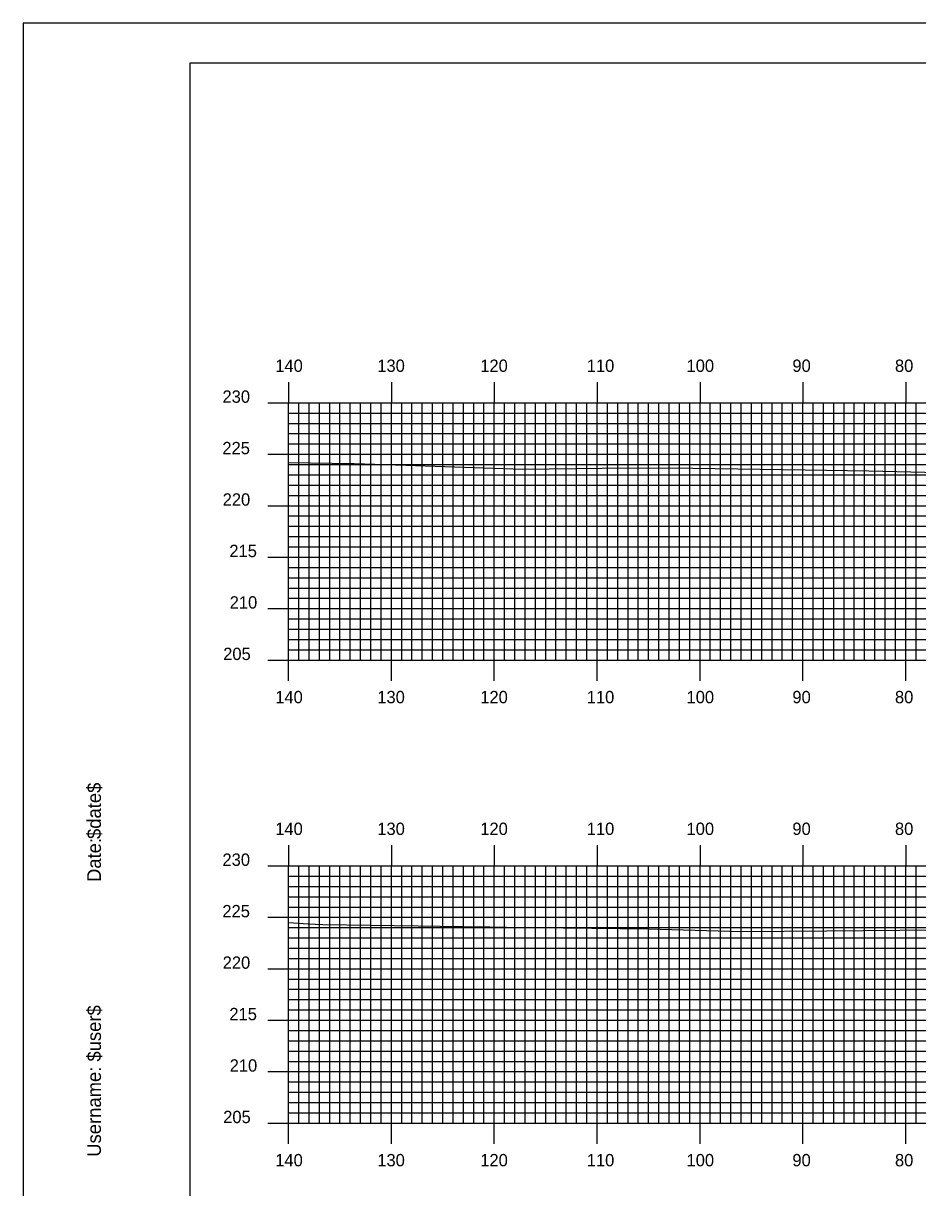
# Model space of a CAD drawing. Extents: x 1820424 to 1820768, y 442591 to 442811.
# Drawn here: x 1820424.4 to 1820511.4, y 442697.4 to 442810.5 of the extents above; entities that cross this region are included whole.
import ezdxf

# ---------------------------------------------------------------- set-up
doc = ezdxf.new("R2010")
doc.units = 0
for name, color, linetype in [('BORDER', 7, 'Continuous'), ('H_V ANNOTATION', 7, 'Continuous'), ('MAJOR', 7, 'Continuous'), ('MINOR', 7, 'Continuous'), ('PLOT BOUNDARY', 7, 'Continuous'), ('S_Roadway_Centerline', 7, 'Continuous')]:
    doc.layers.add(name, color=color, linetype=linetype)

msp = doc.modelspace()

# ---------------------------------------------------------------- linework, layer by layer
at = {"layer": 'BORDER'}
msp.add_lwpolyline([(1820440.6, 442596.67), (1820760.6, 442596.67), (1820760.6, 442806.67), (1820440.6, 442806.67)], close=True, dxfattribs=at)
at = {"layer": 'MAJOR'}
for p, q in [((1820450.2, 442775.67), (1820450.2, 442773.67)), ((1820460.2, 442775.67), (1820460.2, 442773.67)), ((1820470.2, 442775.67), (1820470.2, 442773.67)), ((1820480.2, 442775.67), (1820480.2, 442773.67)), ((1820490.2, 442775.67), (1820490.2, 442773.67)), ((1820500.2, 442775.67), (1820500.2, 442773.67)), ((1820510.2, 442775.67), (1820510.2, 442773.67)), ((1820448.2, 442773.67), (1820450.2, 442773.67)), ((1820450.2, 442773.67), (1820730.2, 442773.67)), ((1820450.2, 442748.67), (1820450.2, 442773.67)), ((1820450.2, 442748.67), (1820450.2, 442773.67)), ((1820450.2, 442773.67), (1820730.2, 442773.67)), ((1820460.2, 442748.67), (1820460.2, 442773.67)), ((1820470.2, 442748.67), (1820470.2, 442773.67)), ((1820480.2, 442748.67), (1820480.2, 442773.67)), ((1820490.2, 442748.67), (1820490.2, 442773.67)), ((1820500.2, 442748.67), (1820500.2, 442773.67)), ((1820510.2, 442748.67), (1820510.2, 442773.67)), ((1820448.2, 442768.67), (1820450.2, 442768.67)), ((1820450.2, 442768.67), (1820730.2, 442768.67)), ((1820448.2, 442763.67), (1820450.2, 442763.67)), ((1820450.2, 442763.67), (1820730.2, 442763.67)), ((1820448.2, 442758.67), (1820450.2, 442758.67)), ((1820450.2, 442758.67), (1820730.2, 442758.67)), ((1820448.2, 442753.67), (1820450.2, 442753.67)), ((1820450.2, 442753.67), (1820730.2, 442753.67)), ((1820448.2, 442748.67), (1820450.2, 442748.67)), ((1820450.2, 442748.67), (1820730.2, 442748.67)), ((1820450.2, 442748.67), (1820730.2, 442748.67)), ((1820450.2, 442746.66), (1820450.2, 442748.67)), ((1820460.2, 442746.66), (1820460.2, 442748.67)), ((1820470.2, 442746.66), (1820470.2, 442748.67)), ((1820480.2, 442746.66), (1820480.2, 442748.67)), ((1820490.2, 442746.66), (1820490.2, 442748.67)), ((1820500.2, 442746.66), (1820500.2, 442748.67)), ((1820510.2, 442746.66), (1820510.2, 442748.67)), ((1820450.2, 442730.67), (1820450.2, 442728.67)), ((1820460.2, 442730.67), (1820460.2, 442728.67)), ((1820470.2, 442730.67), (1820470.2, 442728.67)), ((1820480.2, 442730.67), (1820480.2, 442728.67)), ((1820490.2, 442730.67), (1820490.2, 442728.67)), ((1820500.2, 442730.67), (1820500.2, 442728.67)), ((1820510.2, 442730.67), (1820510.2, 442728.67)), ((1820448.2, 442728.67), (1820450.2, 442728.67)), ((1820450.2, 442728.67), (1820730.2, 442728.67)), ((1820450.2, 442703.67), (1820450.2, 442728.67)), ((1820450.2, 442703.67), (1820450.2, 442728.67)), ((1820450.2, 442728.67), (1820730.2, 442728.67)), ((1820460.2, 442703.67), (1820460.2, 442728.67)), ((1820470.2, 442703.67), (1820470.2, 442728.67)), ((1820480.2, 442703.67), (1820480.2, 442728.67)), ((1820490.2, 442703.67), (1820490.2, 442728.67)), ((1820500.2, 442703.67), (1820500.2, 442728.67)), ((1820510.2, 442703.67), (1820510.2, 442728.67)), ((1820448.2, 442723.67), (1820450.2, 442723.67)), ((1820450.2, 442723.67), (1820730.2, 442723.67)), ((1820448.2, 442718.67), (1820450.2, 442718.67)), ((1820450.2, 442718.67), (1820730.2, 442718.67)), ((1820448.2, 442713.67), (1820450.2, 442713.67)), ((1820450.2, 442713.67), (1820730.2, 442713.67)), ((1820448.2, 442708.67), (1820450.2, 442708.67)), ((1820450.2, 442708.67), (1820730.2, 442708.67)), ((1820448.2, 442703.67), (1820450.2, 442703.67)), ((1820450.2, 442703.67), (1820730.2, 442703.67)), ((1820450.2, 442703.67), (1820730.2, 442703.67)), ((1820450.2, 442701.66), (1820450.2, 442703.67)), ((1820460.2, 442701.66), (1820460.2, 442703.67)), ((1820470.2, 442701.66), (1820470.2, 442703.67)), ((1820480.2, 442701.66), (1820480.2, 442703.67)), ((1820490.2, 442701.66), (1820490.2, 442703.67)), ((1820500.2, 442701.66), (1820500.2, 442703.67)), ((1820510.2, 442701.66), (1820510.2, 442703.67))]:
    msp.add_line(p, q, dxfattribs=at)
at = {"layer": 'MINOR'}
for p, q in [((1820450.2, 442772.67), (1820730.2, 442772.67)), ((1820450.2, 442772.67), (1820452.21, 442772.67)), ((1820451.2, 442748.67), (1820451.2, 442773.67)), ((1820452.2, 442748.67), (1820452.2, 442773.67)), ((1820453.2, 442748.67), (1820453.2, 442773.67)), ((1820454.2, 442748.67), (1820454.2, 442773.67)), ((1820455.2, 442748.67), (1820455.2, 442773.67)), ((1820456.2, 442748.67), (1820456.2, 442773.67)), ((1820457.2, 442748.67), (1820457.2, 442773.67)), ((1820458.2, 442748.67), (1820458.2, 442773.67)), ((1820459.2, 442748.67), (1820459.2, 442773.67)), ((1820461.2, 442748.67), (1820461.2, 442773.67)), ((1820462.2, 442748.67), (1820462.2, 442773.67)), ((1820463.2, 442748.67), (1820463.2, 442773.67)), ((1820464.2, 442748.67), (1820464.2, 442773.67)), ((1820465.2, 442748.67), (1820465.2, 442773.67)), ((1820466.2, 442748.67), (1820466.2, 442773.67)), ((1820467.2, 442748.67), (1820467.2, 442773.67)), ((1820468.2, 442748.67), (1820468.2, 442773.67)), ((1820469.2, 442748.67), (1820469.2, 442773.67)), ((1820471.2, 442748.67), (1820471.2, 442773.67)), ((1820472.2, 442748.67), (1820472.2, 442773.67)), ((1820473.2, 442748.67), (1820473.2, 442773.67)), ((1820474.2, 442748.67), (1820474.2, 442773.67)), ((1820475.2, 442748.67), (1820475.2, 442773.67)), ((1820476.2, 442748.67), (1820476.2, 442773.67)), ((1820477.2, 442748.67), (1820477.2, 442773.67)), ((1820478.2, 442748.67), (1820478.2, 442773.67)), ((1820479.2, 442748.67), (1820479.2, 442773.67)), ((1820481.2, 442748.67), (1820481.2, 442773.67)), ((1820482.2, 442748.67), (1820482.2, 442773.67)), ((1820483.2, 442748.67), (1820483.2, 442773.67)), ((1820484.2, 442748.67), (1820484.2, 442773.67)), ((1820485.2, 442748.67), (1820485.2, 442773.67)), ((1820486.2, 442748.67), (1820486.2, 442773.67)), ((1820487.2, 442748.67), (1820487.2, 442773.67)), ((1820488.2, 442748.67), (1820488.2, 442773.67)), ((1820489.2, 442748.67), (1820489.2, 442773.67)), ((1820491.2, 442748.67), (1820491.2, 442773.67)), ((1820492.2, 442748.67), (1820492.2, 442773.67)), ((1820493.2, 442748.67), (1820493.2, 442773.67)), ((1820494.2, 442748.67), (1820494.2, 442773.67)), ((1820495.2, 442748.67), (1820495.2, 442773.67)), ((1820496.2, 442748.67), (1820496.2, 442773.67)), ((1820497.2, 442748.67), (1820497.2, 442773.67)), ((1820498.2, 442748.67), (1820498.2, 442773.67)), ((1820499.2, 442748.67), (1820499.2, 442773.67)), ((1820501.2, 442748.67), (1820501.2, 442773.67)), ((1820502.2, 442748.67), (1820502.2, 442773.67)), ((1820503.2, 442748.67), (1820503.2, 442773.67)), ((1820504.2, 442748.67), (1820504.2, 442773.67)), ((1820505.2, 442748.67), (1820505.2, 442773.67)), ((1820506.2, 442748.67), (1820506.2, 442773.67)), ((1820507.2, 442748.67), (1820507.2, 442773.67)), ((1820508.2, 442748.67), (1820508.2, 442773.67)), ((1820509.2, 442748.67), (1820509.2, 442773.67)), ((1820511.2, 442748.67), (1820511.2, 442773.67)), ((1820450.2, 442771.67), (1820730.2, 442771.67)), ((1820450.2, 442771.67), (1820452.21, 442771.67)), ((1820450.2, 442770.67), (1820730.2, 442770.67)), ((1820450.2, 442770.67), (1820452.21, 442770.67)), ((1820450.2, 442769.67), (1820730.2, 442769.67)), ((1820450.2, 442769.67), (1820452.21, 442769.67)), ((1820450.2, 442767.67), (1820730.2, 442767.67)), ((1820450.2, 442767.67), (1820452.21, 442767.67)), ((1820450.2, 442766.67), (1820730.2, 442766.67)), ((1820450.2, 442766.67), (1820452.21, 442766.67)), ((1820450.2, 442765.67), (1820730.2, 442765.67)), ((1820450.2, 442765.67), (1820452.21, 442765.67)), ((1820450.2, 442764.67), (1820730.2, 442764.67)), ((1820450.2, 442764.67), (1820452.21, 442764.67)), ((1820450.2, 442762.67), (1820730.2, 442762.67)), ((1820450.2, 442762.67), (1820452.21, 442762.67)), ((1820450.2, 442761.67), (1820730.2, 442761.67)), ((1820450.2, 442761.67), (1820452.21, 442761.67)), ((1820450.2, 442760.67), (1820730.2, 442760.67)), ((1820450.2, 442760.67), (1820452.21, 442760.67)), ((1820450.2, 442759.67), (1820730.2, 442759.67)), ((1820450.2, 442759.67), (1820452.21, 442759.67)), ((1820450.2, 442757.67), (1820730.2, 442757.67)), ((1820450.2, 442757.67), (1820452.21, 442757.67)), ((1820450.2, 442756.67), (1820730.2, 442756.67)), ((1820450.2, 442756.67), (1820452.21, 442756.67)), ((1820450.2, 442755.67), (1820730.2, 442755.67)), ((1820450.2, 442755.67), (1820452.21, 442755.67)), ((1820450.2, 442754.67), (1820730.2, 442754.67)), ((1820450.2, 442754.67), (1820452.21, 442754.67)), ((1820450.2, 442752.67), (1820730.2, 442752.67)), ((1820450.2, 442752.67), (1820452.21, 442752.67)), ((1820450.2, 442751.67), (1820730.2, 442751.67)), ((1820450.2, 442751.67), (1820452.21, 442751.67)), ((1820450.2, 442750.67), (1820730.2, 442750.67)), ((1820450.2, 442750.67), (1820452.21, 442750.67)), ((1820450.2, 442749.67), (1820730.2, 442749.67)), ((1820450.2, 442749.67), (1820452.21, 442749.67)), ((1820451.2, 442703.67), (1820451.2, 442728.67)), ((1820452.2, 442703.67), (1820452.2, 442728.67)), ((1820453.2, 442703.67), (1820453.2, 442728.67)), ((1820454.2, 442703.67), (1820454.2, 442728.67)), ((1820455.2, 442703.67), (1820455.2, 442728.67)), ((1820456.2, 442703.67), (1820456.2, 442728.67)), ((1820457.2, 442703.67), (1820457.2, 442728.67)), ((1820458.2, 442703.67), (1820458.2, 442728.67)), ((1820459.2, 442703.67), (1820459.2, 442728.67)), ((1820461.2, 442703.67), (1820461.2, 442728.67)), ((1820462.2, 442703.67), (1820462.2, 442728.67)), ((1820463.2, 442703.67), (1820463.2, 442728.67)), ((1820464.2, 442703.67), (1820464.2, 442728.67)), ((1820465.2, 442703.67), (1820465.2, 442728.67)), ((1820466.2, 442703.67), (1820466.2, 442728.67)), ((1820467.2, 442703.67), (1820467.2, 442728.67)), ((1820468.2, 442703.67), (1820468.2, 442728.67)), ((1820469.2, 442703.67), (1820469.2, 442728.67)), ((1820471.2, 442703.67), (1820471.2, 442728.67)), ((1820472.2, 442703.67), (1820472.2, 442728.67)), ((1820473.2, 442703.67), (1820473.2, 442728.67)), ((1820474.2, 442703.67), (1820474.2, 442728.67)), ((1820475.2, 442703.67), (1820475.2, 442728.67)), ((1820476.2, 442703.67), (1820476.2, 442728.67)), ((1820477.2, 442703.67), (1820477.2, 442728.67)), ((1820478.2, 442703.67), (1820478.2, 442728.67)), ((1820479.2, 442703.67), (1820479.2, 442728.67)), ((1820481.2, 442703.67), (1820481.2, 442728.67)), ((1820482.2, 442703.67), (1820482.2, 442728.67)), ((1820483.2, 442703.67), (1820483.2, 442728.67)), ((1820484.2, 442703.67), (1820484.2, 442728.67)), ((1820485.2, 442703.67), (1820485.2, 442728.67)), ((1820486.2, 442703.67), (1820486.2, 442728.67)), ((1820487.2, 442703.67), (1820487.2, 442728.67)), ((1820488.2, 442703.67), (1820488.2, 442728.67)), ((1820489.2, 442703.67), (1820489.2, 442728.67)), ((1820491.2, 442703.67), (1820491.2, 442728.67)), ((1820492.2, 442703.67), (1820492.2, 442728.67)), ((1820493.2, 442703.67), (1820493.2, 442728.67)), ((1820494.2, 442703.67), (1820494.2, 442728.67)), ((1820495.2, 442703.67), (1820495.2, 442728.67)), ((1820496.2, 442703.67), (1820496.2, 442728.67)), ((1820497.2, 442703.67), (1820497.2, 442728.67)), ((1820498.2, 442703.67), (1820498.2, 442728.67)), ((1820499.2, 442703.67), (1820499.2, 442728.67)), ((1820501.2, 442703.67), (1820501.2, 442728.67)), ((1820502.2, 442703.67), (1820502.2, 442728.67)), ((1820503.2, 442703.67), (1820503.2, 442728.67)), ((1820504.2, 442703.67), (1820504.2, 442728.67)), ((1820505.2, 442703.67), (1820505.2, 442728.67)), ((1820506.2, 442703.67), (1820506.2, 442728.67)), ((1820507.2, 442703.67), (1820507.2, 442728.67)), ((1820508.2, 442703.67), (1820508.2, 442728.67)), ((1820509.2, 442703.67), (1820509.2, 442728.67)), ((1820511.2, 442703.67), (1820511.2, 442728.67)), ((1820450.2, 442727.67), (1820730.2, 442727.67)), ((1820450.2, 442727.67), (1820452.21, 442727.67)), ((1820450.2, 442726.67), (1820730.2, 442726.67)), ((1820450.2, 442726.67), (1820452.21, 442726.67)), ((1820450.2, 442725.67), (1820730.2, 442725.67)), ((1820450.2, 442725.67), (1820452.21, 442725.67)), ((1820450.2, 442724.67), (1820730.2, 442724.67)), ((1820450.2, 442724.67), (1820452.21, 442724.67)), ((1820450.2, 442722.67), (1820730.2, 442722.67)), ((1820450.2, 442722.67), (1820452.21, 442722.67)), ((1820450.2, 442721.67), (1820730.2, 442721.67)), ((1820450.2, 442721.67), (1820452.21, 442721.67)), ((1820450.2, 442720.67), (1820730.2, 442720.67)), ((1820450.2, 442720.67), (1820452.21, 442720.67)), ((1820450.2, 442719.67), (1820730.2, 442719.67)), ((1820450.2, 442719.67), (1820452.21, 442719.67)), ((1820450.2, 442717.67), (1820730.2, 442717.67)), ((1820450.2, 442717.67), (1820452.21, 442717.67)), ((1820450.2, 442716.67), (1820730.2, 442716.67)), ((1820450.2, 442716.67), (1820452.21, 442716.67)), ((1820450.2, 442715.67), (1820730.2, 442715.67)), ((1820450.2, 442715.67), (1820452.21, 442715.67)), ((1820450.2, 442714.67), (1820730.2, 442714.67)), ((1820450.2, 442714.67), (1820452.21, 442714.67)), ((1820450.2, 442712.67), (1820730.2, 442712.67)), ((1820450.2, 442712.67), (1820452.21, 442712.67)), ((1820450.2, 442711.67), (1820730.2, 442711.67)), ((1820450.2, 442711.67), (1820452.21, 442711.67)), ((1820450.2, 442710.67), (1820730.2, 442710.67)), ((1820450.2, 442710.67), (1820452.21, 442710.67)), ((1820450.2, 442709.67), (1820730.2, 442709.67)), ((1820450.2, 442709.67), (1820452.21, 442709.67)), ((1820450.2, 442707.67), (1820730.2, 442707.67)), ((1820450.2, 442707.67), (1820452.21, 442707.67)), ((1820450.2, 442706.67), (1820730.2, 442706.67)), ((1820450.2, 442706.67), (1820452.21, 442706.67)), ((1820450.2, 442705.67), (1820730.2, 442705.67)), ((1820450.2, 442705.67), (1820452.21, 442705.67)), ((1820450.2, 442704.67), (1820730.2, 442704.67)), ((1820450.2, 442704.67), (1820452.21, 442704.67))]:
    msp.add_line(p, q, dxfattribs=at)
at = {"layer": 'PLOT BOUNDARY'}
msp.add_lwpolyline([(1820424.42, 442590.55), (1820764.42, 442590.55), (1820764.42, 442810.55), (1820424.42, 442810.55)], close=True, dxfattribs=at)
at = {"layer": 'S_Roadway_Centerline'}
for points in [[(1820450.2, 442767.88), (1820454.43, 442767.81), (1820456.57, 442767.78), (1820461.62, 442767.61), (1820472.98, 442767.23), (1820483.25, 442767.34), (1820489.5, 442767.31), (1820500.41, 442767.14), (1820506.6, 442767.04), (1820524.28, 442766.63), (1820540.55, 442766.4), (1820550.14, 442766.1), (1820557.24, 442766.04), (1820570.2, 442765.82), (1820575.02, 442765.8), (1820589.12, 442765.34), (1820606.04, 442764.82), (1820615.95, 442764.71), (1820625.49, 442764.7), (1820631.43, 442764.99), (1820642, 442765.07), (1820655.12, 442764.74)], [(1820450.2, 442723.15), (1820452.1, 442723.03), (1820453.52, 442722.96), (1820462.81, 442722.83), (1820469.22, 442722.74), (1820469.76, 442722.73), (1820471.38, 442722.71), (1820485.18, 442722.55), (1820494.23, 442722.28), (1820502.48, 442722.35), (1820520.29, 442722.53)]]:
    msp.add_lwpolyline(points, dxfattribs=at)

# ---------------------------------------------------------------- texts
at = {"layer": 'BORDER'}
for s, p in [('$date$', (1820431.97, 442731.28)), ('Date:', (1820431.97, 442727.1)), ('$user$', (1820431.97, 442709.65)), ('Username:', (1820431.97, 442700.4))]:
    msp.add_text(s, height=1.339, rotation=90, dxfattribs=at).set_placement(p)
at = {"layer": 'H_V ANNOTATION'}
for s, p in [('140', (1820448.91, 442776.67)), ('130', (1820458.83, 442776.67)), ('120', (1820468.84, 442776.67)), ('110', (1820479.19, 442776.67)), ('100', (1820488.89, 442776.67)), ('90', (1820499.18, 442776.67)), ('80', (1820509.15, 442776.67)), ('230', (1820443.78, 442773.67)), ('225', (1820443.77, 442768.67)), ('220', (1820443.8, 442763.67)), ('215', (1820444.45, 442758.67)), ('210', (1820444.48, 442753.67)), ('205', (1820443.85, 442748.67)), ('140', (1820448.91, 442744.47)), ('130', (1820458.83, 442744.47)), ('120', (1820468.84, 442744.47)), ('110', (1820479.19, 442744.47)), ('100', (1820488.89, 442744.47)), ('90', (1820499.18, 442744.47)), ('80', (1820509.15, 442744.47)), ('140', (1820448.91, 442731.67)), ('130', (1820458.83, 442731.67)), ('120', (1820468.84, 442731.67)), ('110', (1820479.19, 442731.67)), ('100', (1820488.89, 442731.67)), ('90', (1820499.18, 442731.67)), ('80', (1820509.15, 442731.67)), ('230', (1820443.78, 442728.67)), ('225', (1820443.77, 442723.67)), ('220', (1820443.8, 442718.67)), ('215', (1820444.45, 442713.67)), ('210', (1820444.48, 442708.67)), ('205', (1820443.85, 442703.67)), ('140', (1820448.91, 442699.47)), ('130', (1820458.83, 442699.47)), ('120', (1820468.84, 442699.47)), ('110', (1820479.19, 442699.47)), ('100', (1820488.89, 442699.47)), ('90', (1820499.18, 442699.47)), ('80', (1820509.15, 442699.47))]:
    msp.add_text(s, height=1.2, dxfattribs=at).set_placement(p)
at = {"layer": 'MAJOR'}
for p in [(1820450.19, 442748.67), (1820450.19, 442703.67)]:
    msp.add_text('-', height=0.012, dxfattribs=at).set_placement(p)

doc.saveas('drawing.dxf')
